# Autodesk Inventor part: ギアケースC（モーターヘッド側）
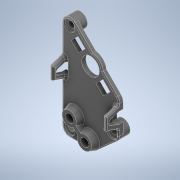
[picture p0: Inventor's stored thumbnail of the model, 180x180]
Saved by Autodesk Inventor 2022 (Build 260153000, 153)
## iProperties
Created: 2024-09
Part Number: ギアケースC（モーターヘッド側）
Material: ABS プラスチック
Document SubType Name: Modeling
Designer: shimizu
Density: 1.06 g/cm^3
Appearance: 滑らか - 白
Author: shimizu
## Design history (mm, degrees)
sketch "スケッチ1"
  geometry: L1 (14, 22)-(14, 8); L2 (0, -4.5)-(-10.5, -4.5); L3 (-14, -1)-(-14, 43); L4 (12.826, 5.385)-(2.991, -3.363); L5 (-8.025, 45.475)-(0.634, 36.816); L6 (5.816, 31.634)-(12.975, 24.475); L7 (-7.676, 38.676)-(8.458, 22.542); L8 (-6.116, 40.652)-(-9.652, 37.116); L9 (-2.581, 37.116)-(-6.116, 33.581); L10 (9.652, 24.884)-(6.116, 21.348); L11 (6.116, 28.419)-(2.581, 24.884); L12 (-9.652, 37.116)-(-6.116, 33.581); L13 (2.581, 24.884)-(6.116, 21.348); L14 (-6.116, 40.652)-(-2.581, 37.116); L15 (6.116, 28.419)-(9.652, 24.884); C1 r 4.35 at (0, 31); A1 r 3.5 centre (-10.5, 43) between (-8.025, 45.475) and (-14, 43); A2 r 4.5 centre (0, 0) between (0, -4.5) and (2.991, -3.363); A3 r 3.5 centre (10.5, 8) between (12.826, 5.385) and (14, 8); A4 r 5.85 centre (0, 31) between (5.816, 31.634) and (0.634, 36.816); A5 r 3.5 centre (10.5, 22) between (14, 22) and (12.975, 24.475); A6 r 3.5 centre (-10.5, -1) between (-14, -1) and (-10.5, -4.5); 1 further point
  constraints: 30 end point, 12 point on circle, 11 tangent, 9 parallel, 7 centre point, 2 perpendicular, 1 coincident, 1 concentric, 1 equal radius, 1 point on line, 1 vertical alignment
  dimensions: "d0" = 7 diameter of A1; "d1" = 43 vertical distance of point (0, 0) A1.centre; "d2" = 9 diameter of A2; "d3" = 14 distance from line of L3 point (0, 0); "d6" = 14 distance from line of L1 point (0, 0); "d7" = 7 diameter of A3; "d8" = 8 vertical distance of point (0, 0) A3.centre; "d9" = 11.7 diameter of A4; "d10" = 31 distance of point (0, 0) A4.centre; "d11" = 8.7 diameter of C1; "d12" = 3.5 radius of A5; "d15" = 5 distance between parallel lines of L9 L8; "d16" = 6.15 distance from line of A4.centre L9; "d17" = 5 distance between parallel lines of L10 L11; "d18" = 6.15 distance from line of A4.centre L11; "d19" = 2.5 distance between parallel lines of L7 L14; "d20" = 2.5 distance between parallel lines of L12 L7
extrude "押し出し1" new body sketch "スケッチ1" distance "d21" = 2; taper "d22" = 0 deg
sketch "スケッチ2"
  geometry: C1 r 3.5 at (10.5, 43); C2 r 3.5 at (-10.5, 8); C3 r 3.5 at (10.5, -1); A1 r 3.5 centre (10.5, 43) between (14, 43) and (8.025, 45.475) reference; A2 r 3.5 centre (-10.5, 8) between (-14, 8) and (-12.826, 5.385) reference; A3 r 3.5 centre (10.5, -1) between (10.5, -4.5) and (14, -1) reference; 1 further point
  constraints: 6 concentric, 3 centre point
extrude "押し出し2" join sketch "スケッチ2" distance "d23" = 3.5; taper "d24" = 0 deg
sketch "スケッチ3"
  geometry: C1 r 3 at (0, 0); C2 r 3 at (0, -44); C3 r 3 at (-21, -35); C4 r 3.5 at (0, 0) reference; C5 r 3.5 at (0, -44) reference; C6 r 3.5 at (-21, -35) reference; 1 further point
  constraints: 3 centre point, 3 concentric, 2 equal radius
  dimensions: "d25" = 6 diameter of C1
extrude "押し出し3" cut sketch "スケッチ3" distance "d26" = 0.5; taper "d27" = 0 deg
sketch "スケッチ4"
  geometry: C1 r 4.5 at (-7.5, 6.5); C2 r 4.5 at (0, 0); 1 further point
  constraints: 2 centre point, 1 coincident, 1 equal radius
  dimensions: "d28" = 9 diameter of C2; "d29" = 6.5 vertical distance of point (0, 0) C1.centre; "d30" = 7.5 horizontal distance of point (0, 0) C1.centre
extrude "押し出し4" join sketch "スケッチ4" distance "d31" = 3; taper "d32" = -18.4 deg
sketch "スケッチ5"
  geometry: L1 (-7.5, 6.5)-(0, 0); L2 (-6.845, 7.256)-(0.655, 0.756); L3 (-8.155, 5.744)-(-0.655, -0.756); L4 (-6.845, 7.256)-(-8.155, 5.744); L5 (0.655, 0.756)-(-0.655, -0.756); C1 r 1.49 at (-7.5, 6.5); C2 r 2.402 at (0, 0); C3 r 3.502 at (-7.5, 6.5) reference; C4 r 3.502 at (0, 0) reference; 5 further points
  constraints: 10 end point, 3 parallel, 2 centre point, 2 coincident, 2 concentric, 2 midpoint, 1 perpendicular
  dimensions: "d33" = 1 distance between parallel lines of L1 L2; "d34" = 1 distance between parallel lines of L3 L1
extrude "押し出し5" join sketch "スケッチ5" stored distance "d35" = 3; taper "d36" = 0 deg
sketch "スケッチ6"
  geometry: C1 r 1.5 at (10.5, 8); C2 r 1.5 at (-10.5, 43); C3 r 1.5 at (-10.5, -1); C4 r 2.05 at (-7.5, 6.5); C5 r 2.05 at (0, 0); A1 r 3.5 centre (-10.5, 43) between (-8.025, 45.475) and (-14, 43) reference; A2 r 3.5 centre (10.5, 8) between (12.826, 5.385) and (14, 8) reference; A3 r 3.5 centre (-10.5, -1) between (-14, -1) and (-10.5, -4.5) reference; A4 r 3.502 centre (-7.5, 6.5) between (-4.309, 5.058) and (-5.619, 3.546) reference; A5 r 3.502 centre (0, 0) between (-3.191, 1.442) and (-1.881, 2.954) reference; 1 further point
  constraints: 5 centre point, 5 concentric, 3 equal radius
  dimensions: "d37" = 3 diameter of C2; "d38" = 4.1 diameter of C4
extrude "押し出し6" cut sketch "スケッチ6" extent not by distance; stored distance "d39" = 3; taper "d40" = 0 deg
sketch "スケッチ7"
  geometry: L1 (-19.54, 8)-(30.961, 8); L2 (-8, 11)-(-8, 5); L3 (-8, 11)-(-2, 13); L4 (-2, 35)-(-2, -9) reference; L5 (-8, 5)-(-2, 3); L6 (-5.974, 9.423)-(-2, 10.748); L7 (-5.974, 6.577)-(-2, 5.252); A1 r 1.5 centre (-5.5, 8) between (-5.974, 9.423) and (-5.974, 6.577); 1 further point
  constraints: 12 end point, 4 point on line, 2 parallel, 2 point on circle, 2 tangent, 1 centre point, 1 horizontal, 1 midpoint, 1 perpendicular, 1 vertical
  dimensions: "d41" = 16 distance from line of point (0, -8) L1; "d42" = 3 distance from line of L1 L2.start; "d43" = 3 distance from line of L1 L2.end; "d44" = 5 distance from line of L1 L3.end; "d45" = 5 distance from line of L1 L5.end; "d46" = 6 distance between parallel lines of L4 L2; "d47" = 3 diameter of A1; "d48" = 3.5 distance from line of L4 A1.centre
extrude "押し出し7" join sketch "スケッチ7" distance "d49" = 2; taper "d50" = 0 deg
sketch "スケッチ8"
  geometry: L1 (-2, 35)-(-2, -9) reference; L2 (0, 0)-(0, 14) reference; L3 (-2, 10.748)-(0, 10.748); L4 (0, 10.748)-(0, 5.252); L5 (0, 5.252)-(-2, 5.252); L6 (-2, 5.252)-(-2, 10.748); 2 further points
  constraints: 8 end point, 2 parallel, 1 horizontal, 1 perpendicular, 1 point on line
extrude "押し出し8" cut sketch "スケッチ8" distance "d51" = 3; taper "d52" = 0 deg
sketch "スケッチ9"
  geometry: L1 (-13.145, 25.5)-(17.511, 25.5); L2 (8, 28.5)-(8, 22.5); L3 (8, 28.5)-(2, 30.5); L4 (2, 25.475)-(2, 32.634) reference; L5 (8, 22.5)-(2, 20.5); L6 (2, 19.748)-(2, 22) reference; L7 (2, 22)-(2, 23) reference; L8 (5.974, 26.923)-(2, 28.248); L9 (5.974, 24.077)-(2, 22.752); L10 (2, 23)-(2, 25.475) reference; A1 r 1.5 centre (5.5, 25.5) between (5.974, 24.077) and (5.974, 26.923); 5 further points
  constraints: 12 end point, 4 point on line, 2 parallel, 2 point on circle, 2 tangent, 1 centre point, 1 horizontal, 1 perpendicular, 2 other
  dimensions: "d53" = 24.5 distance from line of point (0, 1) L1; "d54" = 3 distance from line of L1 L2.start; "d55" = 3 distance from line of L1 L2.end; "d56" = 5 distance from line of L1 L3.end; "d57" = 5 distance from line of L1 L5.end; "d58" = 3 diameter of A1; "d59" = 6 length of L2; "d60" = 3.5 dimension on A1.centre
extrude "押し出し9" join sketch "スケッチ9" distance "d61" = 2; taper "d62" = 0 deg
sketch "スケッチ10"
  geometry: L1 (2, 29.419)-(2, 25.884) reference; L2 (0, 22.348)-(0, 25.884) reference; L3 (2, 28.248)-(0, 28.248); L4 (0, 28.248)-(0, 22.752); L5 (0, 22.752)-(2, 22.752); L6 (2, 22.752)-(2, 28.248); 4 further points
  constraints: 8 end point, 2 parallel, 1 coincident, 1 horizontal, 1 perpendicular, 1 point on line
extrude "押し出し10" cut sketch "スケッチ10" distance "d63" = 3; taper "d64" = 0 deg
fillet "フィレット1" dims "d65" = 1
sketch "スケッチ11"
  geometry: C1 r 2.8 at (-10.5, -1); C2 r 2.8 at (-10.5, 43); C3 r 2.8 at (10.5, 8); C4 r 1.5 at (-10.5, -1) reference; C5 r 1.5 at (10.5, 8) reference; C6 r 1.5 at (-10.5, 43) reference; 1 further point
  constraints: 3 centre point, 3 concentric, 2 equal radius
  dimensions: "d66" = 5.6 diameter of C1
extrude "押し出し11" cut sketch "スケッチ11" distance "d67" = 1; taper "d68" = 0 deg
fillet "フィレット2" dims "d69" = 0.5
node "ソリッド1"
other parameters: "d5" = 45 deg, "d13" = 2.5, "d14" = 2.5
